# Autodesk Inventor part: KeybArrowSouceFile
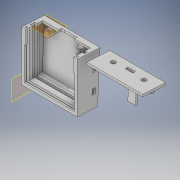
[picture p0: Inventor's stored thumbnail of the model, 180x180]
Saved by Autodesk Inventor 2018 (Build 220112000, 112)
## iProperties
Created: 2018-02
Part Number: KeybArrowSouceFile
Material: Generic
Document SubType Name: Modeling
Designer: Buddy
Density: 1 g/cm^3
Appearance: Default
Author: Buddy
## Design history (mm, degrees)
workplane "Work Plane1"
sketch "Sketch33"
  geometry: L1 (0, 4.5)-(0, 0) reference; L2 (0, 0)-(0, 55.88); L3 (0, 0)-(55.88, 0); L4 (26.728, 78.701)-(25.73, 59.651) reference; L5 (0, 0)-(22.542, -1.181); L6 (0, 0)-(22.573, 0); L7 (22.542, -1.181)-(22.604, 0); L8 (0, 55.88)-(25.462, 54.546); L9 (27.816, 99.453)-(22.604, 0) reference; L10 (22.542, -1.181)-(25.462, 54.546)
  constraints: 14 end point, 2 equal length, 2 horizontal, 1 perpendicular, 1 point on line, 1 vertical
  dimensions: "d147" = 55.88 distance of L1.end L2.end; "d148" = 90 deg angle of L3 L2 (derived); "d149" = 3 deg angle of L5 L6
extrude "This" join sketch "Sketch33" distance "d150" = 2.54; taper "d151" = 0 deg
sketch "Sketch34"
  geometry: L1 (25.462, 54.546)-(0, 55.88) reference; L2 (0, 0)-(22.542, -1.181) reference; L3 (25.462, 54.546)-(22.542, -1.181); L4 (22.542, -1.181)-(0, 0); L5 (0, 0)-(0, 55.88); L6 (0, 55.88)-(1.997, 55.775); L7 (1.997, 55.775)-(1.997, 2.238); L8 (2, 22.551)-(2, 4.5) reference; L9 (1.997, 2.238)-(20.617, 1.262); L10 (20.617, 1.262)-(22.929, 54.678); L11 (20.184, 2.307)-(25.283, 99.585) reference; L12 (25.462, 54.546)-(22.929, 54.678); L13 (27.816, 99.453)-(22.604, 0) reference; 1 further point
  constraints: 16 end point, 3 parallel, 2 perpendicular, 2 point on line, 1 collinear, 1 vertical
  dimensions: "d152" = 2 distance of L5.end L6.end; "d153" = 87 deg angle of L5 L6 (derived)
extrude "File" join sketch "Sketch34" distance "d154" = 57.785; taper "d155" = 0 deg
sketch "Sketch35"
  geometry: L1 (0, 55.88)-(0, 0) reference; L2 (0, 55.88)-(4.445, 55.88); L3 (0, 55.88)-(60.325, 55.88) reference; L4 (4.445, 55.88)-(4.445, 2.54); L5 (60.325, 55.88)-(55.88, 55.88); L6 (55.88, 55.88)-(55.88, 2.54); L7 (55.88, 2.54)-(4.445, 2.54); L8 (4.445, 55.88)-(55.88, 55.88); 1 further point
  constraints: 12 end point, 2 perpendicular, 2 point on line
  dimensions: "d156" = 4.445 distance of L1.start L2.end; "d157" = 53.34 distance of L2.end L4.end; "d159" = 4.445 distance of L3.end L5.end; "d160" = 53.34 distance of L5.end L6.end; "d161" = 90 deg angle of L6 L5 (derived)
extrude "Was" cut sketch "Sketch35" distance "d162" = 5; taper "d163" = 0 deg
sketch "Sketch36"
  geometry: L1 (20.617, 1.262)-(1.997, 2.238) reference; L2 (1.997, 2.238)-(3.995, 2.133); L3 (1.997, 2.238)-(3.997, 2.238); L4 (3.995, 2.133)-(3.995, 4.673); L5 (3.6, 2)-(3.6, 22.051) reference; L6 (3.995, 4.673)-(20.727, 3.796); L7 (22.929, 54.678)-(20.617, 1.262) reference; L8 (20.727, 3.796)-(20.594, 1.263); L9 (20.594, 1.263)-(3.995, 2.133); 1 further point
  constraints: 12 end point, 2 parallel, 2 perpendicular, 2 point on line, 1 collinear, 1 equal length, 1 horizontal
  dimensions: "d164" = 2 distance of L1.end L2.end; "d165" = 3 deg angle of L2 L3 (derived); "d166" = 2.54 distance of L2.end L4.end; "d167" = 87 deg angle of L4 L2 (derived)
extrude "Created/Designed" join sketch "Sketch36" distance "d168" = 58.42; taper "d169" = 0 deg
sketch "Sketch37"
  geometry: L1 (3.995, 2.133)-(3.995, 4.673) reference; L2 (3.995, 4.673)-(3.995, 55.671); L3 (3.995, 4.673)-(5.992, 4.568); L4 (3.995, 4.673)-(20.727, 3.796) reference; L5 (3.995, 4.673)-(5.995, 4.673); L6 (5.992, 4.568)-(5.992, 55.566); L7 (22.929, 54.678)-(1.997, 55.775) reference; L8 (5.992, 55.566)-(3.995, 55.671); 1 further point
  constraints: 10 end point, 2 vertical, 1 collinear, 1 equal length, 1 horizontal, 1 point on line
  dimensions: "d170" = 2 distance of L1.end L3.end; "d171" = 3 deg angle of L3 L5 (derived)
extrude "By" join sketch "Sketch37" distance "d172" = 58.42; taper "d173" = 0 deg
sketch "Sketch38"
  geometry: L1 (-55.88, 53.642)-(-55.88, 0.407) reference; L2 (-55.88, 0.407)-(-4.445, 0.407); L3 (-4.445, 0.407)-(-4.445, 53.803); L4 (-4.445, 53.803)-(-55.88, 53.803); L5 (-55.88, 53.803)-(-55.88, 0.407); 1 further point
  constraints: 8 end point, 2 parallel, 1 horizontal, 1 perpendicular
extrude "Foster Phillips" cut sketch "Sketch38" distance "d174" = 5.08; taper "d175" = 0 deg
sketch "Sketch39"
  geometry: L1 (0, 55.88)-(1.997, 55.775) reference; L2 (0, 55.88)-(25.462, 54.546); L3 (27.816, 99.453)-(22.604, 0) reference; L4 (25.462, 54.546)-(25.462, 52.008); L5 (25.462, 52.008)-(0, 53.342); L6 (0, 58.651)-(0, 39.601) reference; L7 (0, 53.342)-(0, 55.88); 1 further point
  constraints: 8 end point, 2 point on line, 1 collinear, 1 parallel, 1 vertical
extrude "or" join sketch "Sketch39" distance "d176" = 58.42; taper "d177" = 0 deg
sketch "Sketch40"
  geometry: L1 (4.445, 53.028)-(4.445, 4.568) reference; L2 (4.445, 50.919)-(55.88, 50.919); L3 (55.88, 53.133)-(55.88, 2.54) reference; L4 (55.88, 50.919)-(55.88, 55.88); L5 (0, 55.88)-(60.325, 55.88) reference; L6 (4.445, 50.919)-(4.445, 55.88); L7 (4.445, 55.88)-(55.88, 55.88); 1 further point
  constraints: 8 end point, 3 point on line, 2 perpendicular, 1 horizontal, 1 vertical
extrude "Lego_Rocket_08 (Instagram)" cut sketch "Sketch40" distance "d178" = 19.05; taper "d179" = 0 deg
sketch "Sketch41"
  geometry: L1 (1.997, 53.237)-(3.995, 53.133) reference; L2 (1.997, 53.237)-(1.997, 55.775); L3 (19.05, 54.882)-(0, 55.88) reference; L4 (3.995, 53.133)-(3.995, 2.54) reference; L5 (3.995, 53.133)-(1.997, 53.237); L6 (3.995, 53.133)-(3.995, 55.671); L7 (3.995, 55.671)-(1.997, 55.775); 1 further point
  constraints: 8 end point, 2 vertical, 1 parallel, 1 point on line
extrude "I Have" cut sketch "Sketch41" distance "d180" = 58.42; taper "d181" = 0 deg
sketch "Sketch42"
  geometry: L1 (5.992, 53.028)-(5.992, 4.568) reference; L2 (5.992, 53.028)-(3.995, 53.028); L3 (3.995, 55.671)-(3.995, 2.133) reference; L4 (3.995, 53.028)-(9.995, 53.028); L5 (3.995, 53.028)-(9.995, 53.028); L6 (9.995, 53.028)-(9.995, 4.358); L7 (20.727, 3.796)-(5.992, 4.568) reference; L8 (9.995, 4.358)-(3.995, 4.358); L9 (9.995, 4.358)-(15.995, 4.358); L10 (3.995, 4.358)-(3.995, 53.028); 1 further point
  constraints: 14 end point, 3 collinear, 3 horizontal, 2 perpendicular, 2 point on line
  dimensions: "d182" = 6 distance of L2.end L4.end; "d183" = 0 distance between parallel lines of L4 L5 (derived); "d184" = 6 distance of L6.end L8.end; "d185" = 180 deg angle of L8 L9 (derived)
extrude "A Fiverr" join sketch "Sketch42" distance "d186" = 59.055; taper "d187" = 0 deg
sketch "Sketch43"
  geometry: L1 (9.995, 4.358)-(9.995, 52.818) reference; L2 (9.995, 4.358)-(12.99, 4.201); L3 (20.184, 2.307)-(25.283, 99.585) reference; L4 (9.995, 4.358)-(12.995, 4.358); L5 (12.99, 4.201)-(12.99, 52.661); L6 (9.995, 52.818)-(22.82, 52.146) reference; L7 (12.99, 52.661)-(15.527, 52.528); L8 (12.99, 52.661)-(15.53, 52.661); L9 (15.527, 52.528)-(15.527, 4.068); L10 (20.727, 3.796)-(9.995, 4.358) reference; L11 (12.99, 4.201)-(15.527, 4.068); 1 further point
  constraints: 14 end point, 3 parallel, 2 equal length, 2 horizontal, 2 point on line, 1 perpendicular, 1 vertical
  dimensions: "d188" = 3 distance of L1.start L2.end; "d189" = 3 deg angle of L2 L4 (derived); "d190" = 2.54 distance of L5.end L7.end; "d191" = 3 deg angle of L7 L8 (derived)
extrude "If you are" join sketch "Sketch43" distance "d192" = 59.055; taper "d193" = 0 deg
sketch "Sketch44"
  geometry: L1 (-4.445, 50.895)-(-55.88, 50.895) reference; L2 (-55.88, 0.407)-(-55.88, 53.747) reference; L3 (-4.445, 50.895)-(-55.88, 50.895); L4 (-55.88, 50.895)-(-55.88, 2.436); L5 (-55.88, 2.436)-(-4.445, 2.436); L6 (-4.445, 2.436)-(-4.445, 50.895); 1 further point
  constraints: 8 end point, 2 parallel, 1 horizontal, 1 perpendicular, 1 point on line
extrude "Interested" cut sketch "Sketch44" distance "d194" = 11.557; taper "d195" = 0 deg
sketch "Sketch45"
  geometry: L1 (-55.88, 50.396)-(-55.88, 2.436) reference; L2 (-4.445, 53.747)-(-4.445, 0.407) reference; L3 (-55.88, 2.436)-(-4.445, 2.436); L4 (-4.445, 2.436)-(-4.445, 0.407); L5 (-4.445, 0.407)-(-55.88, 0.407); L6 (-55.88, 0.407)-(-55.88, 2.436); 1 further point
  constraints: 8 end point, 2 parallel, 1 horizontal, 1 perpendicular
extrude "In commissions" join sketch "Sketch45" distance "d196" = 5.08; taper "d197" = 0 deg
sketch "Sketch46"
  geometry: L1 (9.995, 4.358)-(9.995, 52.818) reference; L2 (9.995, 4.358)-(9.995, 1.818); L3 (9.6, 4.5)-(9.6, 0) reference; L4 (9.995, 4.358)-(12.535, 4.358); L5 (9.995, 1.818)-(12.99, 1.661); L6 (12.99, 52.661)-(12.99, 4.201) reference; L7 (12.99, 1.661)-(12.99, 4.201); L8 (12.99, 4.201)-(9.995, 4.358); 1 further point
  constraints: 10 end point, 1 horizontal, 1 parallel, 1 perpendicular
  dimensions: "d198" = 2.54 distance of L1.start L2.end; "d199" = 90 deg angle of L2 L4 (derived); "d200" = 3 distance of L2.end L5.end; "d201" = 93 deg angle of L5 L2
extrude "Link is:" cut sketch "Sketch46" distance "d202" = 58.42; taper "d203" = 0 deg
sketch "Sketch47"
  geometry: L1 (9.995, 52.818)-(9.995, 4.568) reference; L2 (9.995, 52.818)-(9.995, 55.356); L3 (25.462, 54.546)-(3.995, 55.671) reference; L4 (12.99, 52.661)-(9.995, 52.818) reference; L5 (9.995, 52.818)-(12.99, 52.661); L6 (12.99, 52.661)-(12.99, 55.199); L7 (12.99, 55.199)-(9.995, 55.356); 1 further point
  constraints: 8 end point, 3 equal length, 1 point on line, 1 vertical
extrude "https://www.fiverr.com/lego_rocket" cut sketch "Sketch47" distance "d204" = 58.42; taper "d205" = 0 deg
sketch "Sketch49"
  geometry: L1 (3.995, 55.671)-(3.995, 4.568) reference; L2 (1.997, 53.237)-(1.997, 55.775) reference; L3 (3.995, 55.671)-(1.997, 55.775); L4 (1.997, 2.238)-(3.995, 2.133) reference; L5 (1.997, 55.775)-(1.997, 2.238); L6 (3.995, 55.671)-(3.995, 2.133) reference; L7 (1.997, 2.238)-(3.995, 2.133); L8 (3.995, 2.133)-(3.995, 55.671); L9 (9.995, 52.818)-(9.995, 55.356) reference; L10 (12.99, 55.199)-(12.99, 1.661) reference; L11 (9.995, 55.356)-(12.99, 55.199); L12 (12.99, 55.199)-(12.99, 1.661); L13 (12.99, 1.661)-(9.995, 1.818) reference; L14 (12.99, 1.661)-(9.995, 1.818); L15 (9.995, 1.818)-(9.995, 55.356); 3 further points
  constraints: 16 end point, 5 equal length
extrude "I Will" cut sketch "Sketch49" distance "d208" = 58.42; taper "d209" = 0 deg
sketch "Sketch50"
  geometry: L1 (0, 55.88)-(0, 2.54) reference; L2 (25.462, 54.546)-(0, 55.88) reference; L3 (0, 55.88)-(25.462, 54.546); L4 (25.462, 54.546)-(25.462, 57.086); L5 (25.462, 57.086)-(0, 58.42); L6 (0, 40.601)-(0, 59.651) reference; L7 (0, 55.88)-(0, 58.42); 1 further point
  constraints: 8 end point, 2 equal length, 1 point on line, 1 vertical
  dimensions: "d212" = 2.54 distance of L2.start L4.end; "d213" = 87 deg angle of L4 L3 (derived)
extrude "Create" join sketch "Sketch50" distance "d214" = 74.93; taper "d215" = 0 deg
sketch "Sketch51"
  geometry: L1 (0, 1.206)-(0, 2.54) reference; L2 (0, -1.334)-(74.93, -1.334) reference; L3 (0, 2.54)-(12.7, 2.54); L4 (12.7, 2.54)-(12.7, -1.334); L5 (12.7, -1.334)-(0, -1.334); L6 (0, -1.334)-(0, 2.54); 1 further point
  constraints: 8 end point, 2 parallel, 1 horizontal, 1 perpendicular, 1 point on line
  dimensions: "d216" = 12.7 distance of L4.end L5.end
extrude "Files" cut sketch "Sketch51" distance "d217" = 73.025; taper "d218" = 0 deg
sketch "Sketch56"
  geometry: L1 (35.365, 5.122)-(26.865, 5.122) reference; L2 (26.865, 5.122)-(35.365, 5.122); L3 (35.365, 5.122)-(35.365, 3.217); L4 (35.365, 3.217)-(26.865, 3.217); L5 (26.865, 3.217)-(26.865, 5.122); 1 further point
  constraints: 8 end point, 2 parallel, 1 horizontal, 1 perpendicular
  dimensions: "d235" = 1.905 distance of L2.end L3.end
extrude "Like this," join sketch "Sketch56" distance "d236" = 30; taper "d237" = 0 deg
sketch "Sketch57"
  geometry: L1 (6, 50.788)-(3.463, 50.921); L2 (6, 50.788)-(0, 51.102) reference; L3 (8.996, -2.907)-(6, -2.75) reference; L4 (6, -2.75)-(3.463, -2.617); L5 (6, -2.75)-(8.54, -2.75); L6 (3.463, -2.617)-(3.463, 50.921); L7 (6, -2.75)-(6, 50.788) reference; L8 (6, 50.788)-(6, -2.75); 1 further point
  constraints: 10 end point, 1 equal length, 1 horizontal, 1 point on line, 1 vertical
  dimensions: "d238" = 2.54 distance of L1.start L1.end; "d239" = 2.54 distance of L3.end L4.end; "d240" = 177 deg angle of L5 L4
extrude "or Type Notes" cut sketch "Sketch57" distance "d241" = 2.54; taper "d242" = 0 deg
node "(especially if they're messy)"
node "Other Links:"
sketch "Sketch65"
  geometry: L1 (27.816, 99.453)-(22.604, 0) reference; L2 (25.462, 52.008)-(25.462, 54.546) reference; L3 (22.604, 0)-(25.462, 54.546); L4 (25.462, 54.546)-(26.312, 54.546); L5 (26.312, 54.546)-(27.645, -0.264); L6 (27.645, -0.264)-(22.604, 0); L7 (22.542, -1.181)-(25.33, 52.015) reference; 1 further point
  constraints: 8 end point, 1 horizontal, 1 perpendicular
extrude "https://www.instagram.com/lego_Rocket_08/" cut sketch "Sketch65" distance "d293" = 76.2; taper "d294" = 0 deg
sketch "Sketch66"
  geometry: L1 (2.982, 0)-(0, 0) reference; L2 (22.604, 0)-(15.6, 0) reference; L3 (0, 0)-(22.604, 0); L4 (22.542, -1.181)-(25.462, 54.546) reference; L5 (0, 0)-(22.542, -1.181); L6 (22.542, -1.181)-(25.462, 54.546); L7 (25.462, 54.546)-(12.99, 55.199); L8 (12.99, 1.661)-(9.995, 1.818) reference; L9 (12.99, 55.199)-(12.99, 1.661); L10 (12.99, 1.661)-(9.995, 1.818); L11 (9.995, 55.356)-(3.995, 55.671) reference; L12 (9.995, 1.818)-(9.995, 55.356); L13 (9.995, 55.356)-(3.995, 55.671); L14 (3.995, 2.133)-(1.997, 2.238) reference; L15 (3.995, 55.671)-(3.995, 2.133); L16 (3.995, 2.133)-(1.997, 2.238); L17 (1.997, 2.238)-(1.997, 55.775); L18 (1.997, 55.775)-(0, 55.88) reference; L19 (1.997, 55.775)-(0, 55.88); L20 (0, 55.88)-(0, 0); L21 (0, 78.701)-(0, 102.79) reference; L22 (15.527, 52.528)-(22.82, 52.146) reference; L23 (22.82, 52.146)-(15.527, 52.528); L24 (20.727, 3.796)-(15.527, 4.068) reference; L25 (15.527, 52.528)-(15.527, 4.068); L26 (15.527, 4.068)-(20.727, 3.796); L27 (20.727, 3.796)-(22.82, 52.146); 2 further points
  constraints: 34 end point, 5 parallel, 3 collinear, 3 perpendicular, 2 vertical, 1 horizontal
extrude "https://www.instructables.com/member/FosterP/" join sketch "Sketch66" distance "d295" = 1.905; taper "d296" = 0 deg
sketch "Sketch67"
  geometry: L1 (0, 0)-(22.542, -1.181) reference; L2 (0, 0)-(22.542, -1.181); L3 (22.542, -1.181)-(22.604, 0); L4 (20.979, -31.006)-(23.733, 21.551) reference; L5 (27.816, 99.453)-(22.604, 0) reference; L6 (0, 4.5)-(0, 0) reference; L7 (22.604, 0)-(0, 0); 1 further point
  constraints: 6 end point, 1 collinear, 1 horizontal, 1 point on line
extrude "Thanks!" join sketch "Sketch67" distance "d297" = 1.905; taper "d298" = 0 deg
sketch "Sketch68"
  geometry: L1 (62.23, 55.775)-(62.23, 55.88) reference; L2 (62.23, 55.88)-(57.785, 55.88); L3 (55.88, 55.88)-(62.23, 55.88) reference; L4 (55.88, 4.568)-(4.445, 4.568) reference; L5 (57.785, 55.88)-(55.88, 55.88); L6 (55.88, 55.88)-(55.88, 4.568); L7 (55.88, 4.568)-(57.785, 4.568); L8 (57.785, 4.568)-(57.785, 55.88); 1 further point
  constraints: 10 end point, 2 parallel, 1 horizontal, 1 perpendicular, 1 point on line
  dimensions: "d299" = 4.445 distance of L1.end L2.end
extrude "..." cut sketch "Sketch68" distance "d300" = 19.05; taper "d301" = 0 deg
sketch "Sketch69"
  geometry: L1 (55.88, 2.54)-(55.88, 4.568) reference; L2 (55.88, 4.568)-(57.785, 4.568); L3 (57.785, 4.568)-(57.785, 2.536); L4 (57.785, 2.536)-(55.88, 2.536); L5 (55.88, 2.536)-(55.88, 4.568); 1 further point
  constraints: 8 end point, 2 parallel, 1 horizontal, 1 perpendicular
  dimensions: "d302" = 1.905 distance of L3.end L4.end; "d303" = 2.032 distance of L2.end L3.end
extrude "Have" cut sketch "Sketch69" distance "d304" = 2.54; taper "d305" = 0 deg
sketch "Sketch70"
  geometry: L1 (0, 4.5)-(0, 0) reference; L2 (0, 0)-(22.542, -1.181); L3 (20.979, -31.006)-(23.733, 21.551) reference; L4 (0, 55.88)-(1.997, 55.775) reference; L5 (0, 0)-(0, 55.88); L6 (0, 55.88)-(25.462, 54.546); L7 (27.816, 99.453)-(22.604, 0) reference; L8 (25.462, 54.546)-(22.542, -1.181); 1 further point
  constraints: 8 end point, 2 point on line, 1 parallel, 1 perpendicular, 1 vertical
extrude "A" join sketch "Sketch70" distance "d306" = 1.905; taper "d307" = 0 deg
sketch "Sketch71"
  geometry: L1 (4.445, 2.54)-(55.88, 2.54) reference; L2 (57.785, 2.536)-(57.785, 55.775) reference; L3 (4.445, 2.54)-(57.785, 2.54); L4 (57.785, 2.54)-(57.785, 3.81); L5 (57.785, 3.81)-(4.445, 3.81); L6 (4.445, 3.81)-(4.445, 2.54); 1 further point
  constraints: 8 end point, 2 parallel, 1 horizontal, 1 perpendicular, 1 point on line
  dimensions: "d308" = 1.27 distance of L4.end L3.end
extrude "Nice" join sketch "Sketch71" distance "d309" = 1.905; taper "d310" = 0 deg
sketch "Sketch72"
  geometry: L1 (57.915, 2.4)-(55.61, 2.4); L2 (55.61, 2.4)-(55.61, 2.876); L3 (55.61, 2.876)-(57.915, 2.876); L4 (57.915, 2.876)-(57.915, 2.4); 1 further point
  constraints: 8 end point, 2 parallel, 1 horizontal, 1 perpendicular
extrude "Day!" join sketch "Sketch72" distance "d311" = 1.905; taper "d312" = 0 deg
sketch "Sketch73"
  geometry: L1 (26.865, 5.122)-(35.365, 5.122) reference; L2 (26.865, 5.122)-(26.865, 6.646); L3 (26.865, 6.646)-(35.365, 6.646); L4 (35.365, 6.646)-(35.365, 9.646); L5 (35.365, 9.646)-(26.865, 9.646); L6 (26.865, 9.646)-(26.865, 6.646); 1 further point
  constraints: 10 end point, 3 perpendicular, 1 collinear, 1 point on line, 1 vertical
  dimensions: "d313" = 1.524 distance of L1.start L2.end; "d314" = 3 distance of L3.end L4.end
extrude "Extrusion73" cut sketch "Sketch73" distance "d315" = 25.4; taper "d316" = 0 deg
sketch "Sketch74"
  geometry: L1 (20.727, 3.796)-(22.82, 52.146) reference; L2 (20.982, 9.692)-(14.99, 10.006); L3 (20.982, 9.692)-(26.982, 9.692); L4 (14.99, 10.006)-(15.592, 21.49); L5 (14.99, 10.006)-(26.49, 10.006); L6 (15.592, 21.49)-(21.479, 21.182); L7 (21.479, 21.182)-(20.982, 9.692); L8 (21.479, 21.182)-(21.715, 25.675); L9 (21.479, 21.182)-(25.979, 21.182); L10 (21.715, 25.675)-(20.716, 25.623); L11 (21.715, 25.675)-(22.715, 25.675); L12 (20.716, 25.623)-(20.486, 21.234); L13 (20.982, 9.692)-(20.982, 5.192); L14 (20.982, 9.692)-(25.482, 9.692); L15 (20.982, 5.192)-(19.982, 5.192); L16 (19.982, 5.192)-(19.884, 9.749); L17 (21.723, 26.807)-(20.724, 26.86); L18 (21.723, 26.807)-(22.723, 26.807); L19 (20.724, 26.86)-(20.96, 31.353); L20 (22.249, 54.714)-(20.679, 24.755) reference; L21 (20.96, 31.353)-(21.917, 31.303); L22 (21.917, 31.303)-(21.723, 26.807); L23 (21.917, 31.303)-(15.926, 31.617); L24 (21.917, 31.303)-(27.917, 31.303); L25 (15.926, 31.617)-(16.527, 43.101); L26 (16.527, 43.101)-(22.415, 42.793); L27 (21.917, 31.303)-(22.415, 42.793); L28 (22.415, 42.793)-(22.65, 47.287); L29 (22.415, 42.793)-(26.915, 42.793); L30 (22.65, 47.287)-(21.652, 47.339); L31 (21.652, 47.339)-(21.416, 42.845); 1 further point
  constraints: 58 end point, 9 perpendicular, 9 point on line, 8 equal length, 8 horizontal, 4 collinear, 1 parallel, 1 vertical
  dimensions: "d317" = 6 distance of L2.start L2.end; "d318" = 177 deg angle of L3 L2; "d319" = 11.5 distance of L2.end L4.end; "d320" = 87 deg angle of L5 L4; "d321" = 90 deg angle of L4 L6; "d322" = 4.5 distance of L6.end L8.end; "d323" = 87 deg angle of L9 L8 (derived); "d324" = 1 distance of L8.end L10.end; "d325" = 177 deg angle of L10 L11; "d326" = 4.5 distance of L2.start L13.end; "d327" = 90 deg angle of L13 L14 (derived); "d328" = 1 distance of L13.end L15.end; "d329" = 90 deg angle of L13 L15 (derived); "d330" = 1 distance of L17.start L17.end; "d331" = 177 deg angle of L18 L17 (derived); "d332" = 4.5 distance of L17.end L19.end; "d333" = 90 deg angle of L17 L19 (derived); "d334" = 90 deg angle of L19 L21; "d335" = 6 distance of L21.end L23.end; "d336" = 177 deg angle of L24 L23 (derived); "d337" = 11.5 distance of L23.end L25.end; "d338" = 4.5 distance of L26.end L28.end; "d339" = 87 deg angle of L29 L28 (derived); "d340" = 1 distance of L28.end L30.end; "d341" = 90 deg angle of L30 L28 (derived)
extrude "Extrusion74" cut sketch "Sketch74" distance "d342" = 2.54; taper "d343" = 0 deg
sketch "Sketch75"
  geometry: L1 (15.926, 31.617)-(16.527, 43.101) reference; L2 (16.227, 37.359)-(22.166, 37.048); L3 (22.415, 42.793)-(21.723, 26.807) reference; L4 (16.227, 37.359)-(22.174, 37.359); L5 (19.2, 37.359)-(17.45, 37.359); L6 (19.2, 37.359)-(20.95, 37.359); L7 (17.45, 37.359)-(17.62, 40.605); L8 (16.527, 43.101)-(21.416, 42.845) reference; L9 (17.62, 40.605)-(21.116, 40.422); L10 (21.116, 40.422)-(20.775, 33.931); L11 (21.116, 40.422)-(27.616, 40.422); L12 (20.775, 33.931)-(17.28, 34.114); L13 (17.28, 34.114)-(17.62, 40.605); L14 (19.884, 9.749)-(14.99, 10.006) reference; L15 (20.486, 21.234)-(15.592, 21.49) reference; L16 (20.184, 2.307)-(25.283, 99.585) reference; L17 (21.231, 15.437)-(15.291, 15.748); L18 (14.99, 10.006)-(15.527, 20.246) reference; L19 (18.261, 15.592)-(16.513, 15.684); L20 (18.261, 15.592)-(20.011, 15.592); L21 (16.513, 15.684)-(16.683, 18.929); L22 (16.683, 18.929)-(20.179, 18.746); L23 (20.179, 18.746)-(19.838, 12.255); L24 (19.838, 12.255)-(16.343, 12.438); L25 (16.343, 12.438)-(16.683, 18.929); L26 (17.28, 34.114)-(17.62, 40.605); L27 (21.116, 40.422)-(17.62, 40.605); L28 (21.116, 40.422)-(20.775, 33.931); L29 (20.775, 33.931)-(17.28, 34.114); L30 (22.174, 3.184)-(24.612, 49.694); L31 (22.249, 54.714)-(20.679, 24.755) reference; L32 (24.612, 49.694)-(13.282, 50.288); L33 (13.282, 50.288)-(13.282, 26.807); L34 (15.527, 4.568)-(15.527, 52.528) reference; L35 (13.282, 26.807)-(14.653, 3.578); L36 (14.653, 3.578)-(22.174, 3.184); 1 further point
  constraints: 54 end point, 11 perpendicular, 4 collinear, 4 equal length, 4 horizontal, 3 midpoint, 3 point on line, 2 parallel
  dimensions: "d344" = 3 deg angle of L2 L4; "d345" = 1.75 distance of L5.start L5.end; "d346" = 180 deg angle of L5 L6 (derived); "d347" = 3.25 distance of L5.end L7.end; "d348" = 87 deg angle of L5 L7 (derived); "d349" = 3.5 distance of L7.end L9.end; "d350" = 6.5 distance of L9.end L10.end; "d351" = 93 deg angle of L10 L11; "d352" = 1.75 distance of L19.start L19.end; "d353" = 177 deg angle of L20 L19; "d354" = 3.25 distance of L19.end L21.end; "d355" = 90 deg angle of L19 L21 (derived); "d356" = 3.5 distance of L21.end L22.end; "d357" = 90 deg angle of L21 L22 (derived); "d358" = 6.5 distance of L22.end L23.end; "d359" = 90 deg angle of L22 L23 (derived)
extrude "Extrusion75" join sketch "Sketch75" distance "d360" = 1.27; taper "d361" = 0 deg
sketch "Sketch76"
  geometry: L1 (55.245, 0.034)-(1.905, 0.034) reference; L2 (48.262, 0.034)-(43.182, 0.034); L3 (43.182, 0.034)-(43.182, -5.046); L4 (43.182, -5.046)-(48.262, -5.046); L5 (48.262, -5.046)-(48.262, 0.034); L6 (1.905, -47.849)-(55.245, -47.849) reference; L7 (28.575, -47.849)-(28.575, 0.034); L8 (8.888, 0.034)-(13.968, 0.034); L9 (13.968, 0.034)-(13.968, -5.046); L10 (13.968, -5.046)-(8.888, -5.046); L11 (8.888, -5.046)-(8.888, 0.034); 1 further point
  constraints: 18 end point, 4 symmetric about line, 2 midpoint, 2 parallel, 1 horizontal, 1 perpendicular, 1 point on line
  dimensions: "d362" = 5.08 distance of L4.end L3.end; "d363" = 5.08 distance of L3.end L2.end
extrude "Extrusion76" join sketch "Sketch76" distance "d364" = 10.16; taper "d365" = 0 deg
sketch "Sketch77"
  geometry: L1 (0, -6.385)-(5.08, -6.385) reference; L2 (2.54, -6.385)-(2.54, -3.845); L3 (-41.277, -0.11)-(12.063, -0.11) reference; L4 (-14.607, -0.11)-(-14.607, -16.934); L5 (12.063, -16.934)-(-41.277, -16.934) reference; L6 (-29.214, -6.385)-(-34.294, -6.385); L7 (-31.754, -6.385)-(-31.754, -3.845); C1 r 1.27 at (2.54, -3.845); C2 r 1.27 at (-31.754, -3.845); 1 further point
  constraints: 8 end point, 5 symmetric about line, 3 midpoint, 2 centre point, 2 coincident, 1 vertical, 1 other
  dimensions: "d366" = 2.54 distance of L2.start L2.end; "d367" = 2.54 diameter of C1
extrude "Extrusion77" cut sketch "Sketch77" distance "d368" = 5.08; taper "d369" = 0 deg
sketch "Sketch78"
  geometry: L1 (135.255, 0)-(135.255, 25.497) reference; L2 (135.255, 25.497)-(121.285, 25.497); L3 (73.025, 25.497)-(135.255, 25.497) reference; L4 (135.255, 25.497)-(149.225, 25.497); L5 (121.285, 25.497)-(121.285, 15.337); L6 (73.025, 0)-(135.255, 0) reference; L7 (104.14, 0)-(104.14, 25.497); L8 (73.025, 0)-(73.025, 25.497); L9 (73.025, 25.497)-(86.995, 25.497); L10 (73.025, 25.497)-(59.055, 25.497); L11 (86.995, 25.497)-(86.995, 15.337); C1 r 2.54 at (121.285, 15.337); C2 r 2.54 at (86.995, 15.337); 1 further point
  constraints: 16 end point, 4 symmetric about line, 2 centre point, 2 coincident, 2 collinear, 2 midpoint, 1 horizontal, 1 perpendicular, 1 other
  dimensions: "d370" = 13.97 distance of L1.end L2.end; "d371" = 180 deg angle of L2 L4 (derived); "d372" = 10.16 distance of L2.end L5.end; "d373" = 5.08 diameter of C1
extrude "Extrusion78" cut sketch "Sketch78" distance "d374" = 5.08; taper "d375" = 0 deg
sketch "Sketch79"
  geometry: C1 r 2.54 at (13.97, 10.16) reference; C2 r 1.27 at (13.97, 10.16); C3 r 2.54 at (13.97, 10.16); C4 r 2.54 at (48.26, 10.16) reference; C5 r 1.27 at (48.26, 10.16); C6 r 2.54 at (48.26, 10.16); 1 further point
  constraints: 4 centre point, 4 coincident
  dimensions: "d376" = 2.54 diameter of C2; "d377" = 2.54 diameter of C5
extrude "Extrusion79" join sketch "Sketch79" distance "d378" = 1.016; taper "d379" = 0 deg
sketch "Sketch80"
  geometry: L1 (0, 0)-(62.23, 0) reference; L2 (0, 0)-(5.08, 0); L3 (5.08, 0)-(5.08, 6.35); L4 (5.08, 6.35)-(8.89, 6.35); L5 (8.89, 6.35)-(8.89, 10.16); L6 (8.89, 10.16)-(5.08, 10.16); L7 (5.08, 10.16)-(5.08, 6.35); L8 (0, 25.63)-(62.23, 25.63) reference; L9 (31.115, 25.63)-(31.115, 0); L10 (57.15, 6.35)-(53.34, 6.35); L11 (53.34, 6.35)-(53.34, 10.16); L12 (53.34, 10.16)-(57.15, 10.16); L13 (57.15, 10.16)-(57.15, 6.35); 1 further point
  constraints: 22 end point, 4 symmetric about line, 2 midpoint, 2 parallel, 1 horizontal, 1 perpendicular, 1 point on line, 1 vertical
  dimensions: "d380" = 5.08 distance of L1.start L2.end; "d381" = 6.35 distance of L2.end L3.end; "d382" = 3.81 distance of L6.end L5.end; "d383" = 3.81 distance of L5.end L4.end
extrude "Extrusion80" join sketch "Sketch80" distance "d384" = 6.35; taper "d385" = 0 deg
sketch "Sketch82"
  geometry: L1 (45.722, 19.209)-(16.508, 19.209) reference; L2 (31.115, 19.209)-(31.115, 25.497); L3 (0, 25.497)-(62.23, 25.497) reference; L4 (31.115, 19.209)-(26.035, 19.209); L5 (26.035, 19.209)-(26.035, 22.384); L6 (26.035, 22.384)-(31.115, 22.384); L7 (31.115, 22.384)-(31.115, 19.209); L8 (31.115, 19.209)-(36.195, 19.209); L9 (36.195, 19.209)-(36.195, 22.384); L10 (36.195, 22.384)-(31.115, 22.384); L11 (31.115, 22.384)-(31.115, 19.209); L12 (4.445, 19.076)-(57.785, 19.076) reference; L13 (36.195, 19.209)-(26.035, 19.209); L14 (26.035, 19.209)-(26.035, 19.076); L15 (26.035, 19.076)-(36.195, 19.076); L16 (36.195, 19.076)-(36.195, 19.209); L17 (26.035, 19.076)-(22.225, 19.076); L18 (22.225, 19.076)-(22.225, 22.378); L19 (22.225, 22.378)-(26.035, 22.378); L20 (26.035, 22.378)-(26.035, 19.076); L21 (36.195, 19.076)-(40.005, 19.076); L22 (40.005, 19.076)-(40.005, 22.378); L23 (40.005, 22.378)-(36.195, 22.378); L24 (36.195, 22.378)-(36.195, 19.076); 1 further point
  constraints: 42 end point, 10 parallel, 5 horizontal, 5 perpendicular, 2 midpoint, 1 point on line
  dimensions: "d388" = 5.08 distance of L5.end L6.end; "d389" = 3.175 distance of L4.end L5.end; "d390" = 5.08 distance of L10.end L9.end; "d391" = 3.175 distance of L9.end L8.end; "d392" = 3.81 distance of L18.end L19.end; "d393" = 3.302 distance of L17.end L18.end; "d394" = 3.81 distance of L23.end L22.end; "d395" = 3.302 distance of L22.end L21.end
extrude "Extrusion82" cut sketch "Sketch82" distance "d396" = 3.81; taper "d397" = 0 deg
sketch "Sketch84"
  geometry: L1 (4.445, 3.81)-(57.785, 3.81) reference; L2 (4.445, 3.81)-(3.175, 3.81); L3 (0, 55.88)-(4.445, 55.88) reference; L4 (3.175, 55.88)-(3.175, 40.386); L5 (1.905, 1.951)-(1.905, 55.489) reference; L6 (3.175, 55.88)-(18.669, 55.88); L7 (3.175, 40.386)-(3.175, 3.81); L8 (3.175, 40.386)-(4.445, 40.386); L9 (4.445, 4.568)-(4.445, 55.489) reference; L10 (4.445, 40.386)-(4.445, 3.81); L11 (2.54, 52.528)-(2.54, 4.068) reference; L12 (26.035, 54.709)-(36.195, 54.709) reference; L13 (31.115, 54.709)-(31.115, 3.81); L14 (59.055, 40.386)-(57.785, 40.386); L15 (59.055, 55.88)-(59.055, 40.386); L16 (57.785, 4.568)-(57.785, 55.489); L17 (60.325, 1.951)-(60.325, 55.489); L18 (59.69, 52.528)-(59.69, 4.068); L19 (59.055, 40.386)-(59.055, 3.81); L20 (57.785, 40.386)-(57.785, 3.81); L21 (59.055, 3.81)-(57.785, 3.81); L22 (60.325, 3.796)-(2.54, 3.796) reference; 1 further point
  constraints: 30 end point, 10 symmetric about line, 3 parallel, 3 point on line, 2 horizontal, 2 midpoint, 2 perpendicular, 1 collinear
  dimensions: "d398" = 1.27 distance of L1.start L2.end; "d399" = 15.494 distance of L4.start L4.end; "d400" = 90 deg angle of L4 L6 (derived)
extrude "Extrusion83" cut sketch "Sketch84" distance "d401" = 2.54; taper "d402" = 0 deg
sketch "Sketch86"
  geometry: L1 (25.462, 54.546)-(0, 55.88) reference; L2 (0, 55.88)-(3.938, 55.674); L3 (3.938, 55.674)-(4.002, 56.901); L4 (4.002, 56.901)-(0, 57.11); L5 (0, 40.601)-(0, 59.651) reference; L6 (0, 55.88)-(0, 57.11); 1 further point
  constraints: 8 end point, 2 perpendicular, 2 point on line, 1 vertical
extrude "Extrusion85" cut sketch "Sketch86" distance "d406" = 63.5; taper "d407" = 0 deg
fillet "Fillet2" dims "d408" = 2.54
sketch "Sketch87"
  geometry: C1 r 1.27 at (2.54, -3.845) reference; C2 r 1.524 at (2.54, -3.845); C3 r 1.27 at (-31.754, -3.845) reference; C4 r 1.524 at (-31.754, -3.845); 1 further point
  constraints: 2 centre point, 2 coincident
  dimensions: "d409" = 3.048 diameter of C2; "d410" = 3.048 diameter of C4
extrude "Extrusion86" cut sketch "Sketch87" distance "d411" = 6.35; taper "d412" = 0 deg
sketch "Sketch89"
  geometry: L1 (31.217, -1.761)-(22.94, -1.761); L2 (22.94, -1.761)-(22.94, -1.086); L3 (22.94, -1.086)-(31.217, -1.086); L4 (31.217, -1.086)-(31.217, -1.761); 1 further point
  constraints: 2 other
extrude "Extrusion88" cut sketch "Sketch89" distance "d415" = 0.00254; taper "d416" = 0 deg
body "Solid1"
